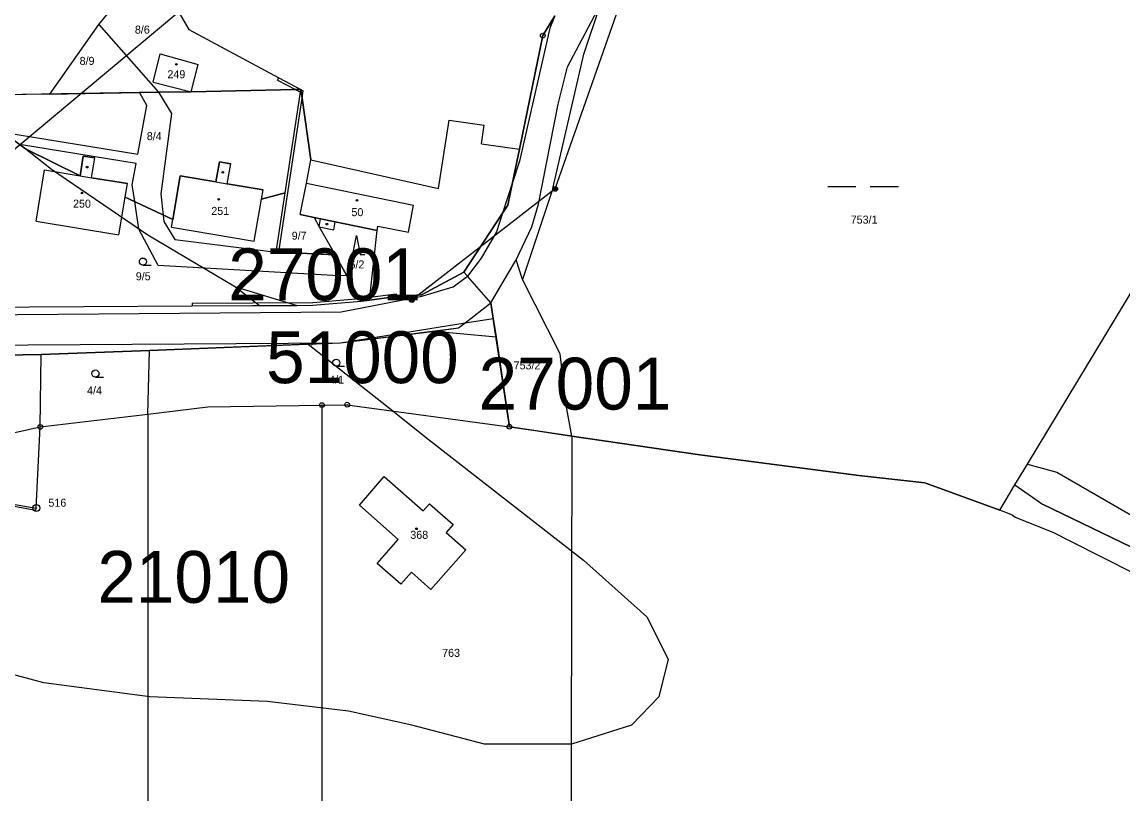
# Model space of a CAD drawing. Extents: x -725765 to -723182, y -1052705 to -1049154.
# Drawn here: x -724492.6 to -724259, y -1051095.6 to -1050931.8 of the extents above; entities that cross this region are included whole.
import ezdxf

# ---------------------------------------------------------------- set-up
doc = ezdxf.new("R2010")
doc.units = 0
for name, color, linetype in [('Vrstva 1', 7, 'Continuous'), ('Vrstva 12', 7, 'Continuous'), ('Vrstva 17', 7, 'Continuous'), ('Vrstva 18', 7, 'Continuous'), ('Vrstva 19', 7, 'Continuous'), ('Vrstva 25', 7, 'Continuous'), ('Vrstva 27', 7, 'Continuous'), ('Vrstva 4', 7, 'Continuous'), ('Vrstva 52', 7, 'Continuous'), ('Vrstva 53', 7, 'Continuous')]:
    doc.layers.add(name, color=color, linetype=linetype)

msp = doc.modelspace()

# ---------------------------------------------------------------- linework, layer by layer
at = {"layer": 'Vrstva 1'}
for points in [[(-724476.27, -1050932.34), (-724466.99, -1050921.02)], [(-724462.55, -1050923.98), (-724457.15, -1050933.43)], [(-724376.7, -1050941.33), (-724369.69, -1050928.08)], [(-724486.65, -1050947.12), (-724476.27, -1050932.34)], [(-724476.27, -1050932.34), (-724463.55, -1050946.69)], [(-724381.97, -1050934.69), (-724379.43, -1050930.49)], [(-724457.15, -1050933.43), (-724438.01, -1050943.64)], [(-724386.92, -1050958.77), (-724381.97, -1050934.69)], [(-724464.71, -1050944.56), (-724463.24, -1050938.58)], [(-724463.24, -1050938.58), (-724455.15, -1050940.8)], [(-724456.63, -1050946.64), (-724455.15, -1050940.8)], [(-724378.71, -1050949.25), (-724376.7, -1050941.33)], [(-724279.02, -1051025.59), (-724228.49, -1050942.01)], [(-724438.01, -1050943.64), (-724433.33, -1050946.13)], [(-724486.65, -1050947.12), (-724467.73, -1050946.77), (-724463.55, -1050946.69)], [(-724464.71, -1050944.56), (-724456.63, -1050946.64)], [(-724463.55, -1050946.69), (-724456.63, -1050946.64)], [(-724456.63, -1050946.64), (-724434.45, -1050946.15)], [(-724436.68, -1050968.08), (-724433.42, -1050946.7)], [(-724434.45, -1050946.15), (-724433.33, -1050946.13)], [(-724433.42, -1050946.7), (-724433.33, -1050946.13)], [(-724433.33, -1050946.13), (-724433.06, -1050947.99)], [(-724486.65, -1050947.12), (-724496.66, -1050947.3)], [(-724433.06, -1050947.99), (-724431.19, -1050961.03)], [(-724382.9, -1050970.46), (-724378.71, -1050949.25)], [(-724498.57, -1050953.71), (-724491.8, -1050958.69)], [(-724404.11, -1050967.13), (-724401.86, -1050952.66)], [(-724401.86, -1050952.66), (-724394.42, -1050953.7)], [(-724394.95, -1050957.67), (-724394.42, -1050953.7)], [(-724394.95, -1050957.67), (-724386.92, -1050958.77)], [(-724491.8, -1050958.69), (-724480.19, -1050964.45)], [(-724480.19, -1050964.45), (-724479.54, -1050960.25)], [(-724479.54, -1050960.25), (-724477.11, -1050960.65)], [(-724477.77, -1050964.85), (-724477.11, -1050960.65)], [(-724388.38, -1050965.85), (-724386.92, -1050958.77)], [(-724451.36, -1050965.74), (-724450.61, -1050961.47)], [(-724450.61, -1050961.47), (-724448.22, -1050961.87)], [(-724448.96, -1050966.14), (-724448.22, -1050961.87)], [(-724432.16, -1050965.97), (-724431.19, -1050961.03)], [(-724431.19, -1050961.03), (-724404.11, -1050967.13)], [(-724489.56, -1050974.07), (-724487.78, -1050963.2)], [(-724487.78, -1050963.2), (-724480.19, -1050964.45)], [(-724477.77, -1050964.85), (-724470.18, -1050966.1)], [(-724460.55, -1050973.74), (-724458.96, -1050964.48)], [(-724458.96, -1050964.48), (-724451.36, -1050965.74)], [(-724470.65, -1050968.96), (-724470.18, -1050966.1)], [(-724448.96, -1050966.14), (-724441.36, -1050967.41)], [(-724441.7, -1050969.38), (-724441.36, -1050967.41)], [(-724433.48, -1050972.68), (-724432.16, -1050965.97)], [(-724389.37, -1050970.69), (-724388.38, -1050965.85)], [(-724471.98, -1050976.99), (-724470.65, -1050968.96)], [(-724470.65, -1050968.96), (-724460.55, -1050973.74)], [(-724443.22, -1050978.31), (-724441.7, -1050969.38)], [(-724441.7, -1050969.38), (-724436.68, -1050968.08)], [(-724438.59, -1050980.62), (-724436.68, -1050968.08)], [(-724398.72, -1050984.87), (-724390.49, -1050972.39)], [(-724390.49, -1050972.39), (-724389.37, -1050970.69)], [(-724384.31, -1050975.24), (-724382.9, -1050970.46)], [(-724489.56, -1050974.07), (-724471.98, -1050976.99)], [(-724460.82, -1050975.33), (-724460.55, -1050973.74)], [(-724433.48, -1050972.68), (-724430.53, -1050973.29)], [(-724430.53, -1050973.29), (-724429.14, -1050973.57)], [(-724430.53, -1050973.29), (-724429.42, -1050975.26)], [(-724429.14, -1050973.57), (-724426.05, -1050974.21)], [(-724426.05, -1050974.21), (-724417.16, -1050976.04)], [(-724460.82, -1050975.33), (-724443.22, -1050978.31)], [(-724429.42, -1050975.26), (-724426.05, -1050981.21)], [(-724418.7, -1050990.2), (-724417.16, -1050976.04)], [(-724387.6, -1050982.26), (-724384.31, -1050975.24)], [(-724438.59, -1050980.62), (-724438.04, -1050980.65)], [(-724438.04, -1050980.65), (-724426.05, -1050981.21)], [(-724426.05, -1050981.21), (-724420.88, -1050990.48)], [(-724392.98, -1050991.37), (-724387.6, -1050982.26)], [(-724386.28, -1050986.41), (-724387.6, -1050982.26)], [(-724407.7, -1050989.71), (-724398.72, -1050984.87)], [(-724397.93, -1050985.76), (-724398.72, -1050984.87)], [(-724392.98, -1050991.37), (-724397.93, -1050985.76)], [(-724375.8, -1051019.67), (-724377.02, -1051013.07), (-724378.31, -1051002.23), (-724386.28, -1050986.41)], [(-724430.78, -1050991.92), (-724420.56, -1050991.06)], [(-724420.88, -1050990.48), (-724420.56, -1050991.06)], [(-724420.56, -1050991.06), (-724418.77, -1050990.82)], [(-724418.77, -1050990.82), (-724413.02, -1050990.06)], [(-724418.77, -1050990.82), (-724418.7, -1050990.2)], [(-724413.02, -1050990.06), (-724407.7, -1050989.71)], [(-724502.49, -1050992.29), (-724456.42, -1050992.05)], [(-724456.42, -1050992.05), (-724430.78, -1050991.92)], [(-724398.47, -1050995.65), (-724392.98, -1050991.37)], [(-724392.48, -1050994.69), (-724392.98, -1050991.37)], [(-724399.85, -1050996.73), (-724398.47, -1050995.65)], [(-724389.04, -1051017.67), (-724392.48, -1050994.69)], [(-724424.9, -1050999.89), (-724399.85, -1050996.73)], [(-724465.46, -1051001.47), (-724424.9, -1050999.89)], [(-724534.5, -1051003.23), (-724488.46, -1051002.37)], [(-724488.68, -1051017.73), (-724488.46, -1051002.37)], [(-724488.46, -1051002.37), (-724465.46, -1051001.47)], [(-724465.84, -1051014.99), (-724465.46, -1051001.47)], [(-724465.84, -1051014.99), (-724453.07, -1051013.46)], [(-724453.07, -1051013.46), (-724428.87, -1051013.08)], [(-724428.87, -1051013.08), (-724423.49, -1051013)], [(-724428.87, -1051013.08), (-724428.86, -1051121.56)], [(-724423.49, -1051013), (-724389.04, -1051017.67)], [(-724488.68, -1051017.73), (-724465.84, -1051014.99)], [(-724465.84, -1051014.99), (-724465.82, -1051346.13)], [(-724516.35, -1051023.82), (-724488.68, -1051017.73)], [(-724489.51, -1051034.92), (-724488.68, -1051017.73)], [(-724375.8, -1051019.67), (-724389.04, -1051017.67)], [(-724375.8, -1051019.67), (-724376.03, -1051121.56)], [(-724348.61, -1051023.67), (-724375.8, -1051019.67)], [(-724314.87, -1051028.04), (-724348.61, -1051023.67)], [(-724281.71, -1051030.03), (-724279.02, -1051025.59)], [(-724279.02, -1051025.59), (-724272.83, -1051027.29)], [(-724420.92, -1051034.33), (-724415.63, -1051028.25)], [(-724415.63, -1051028.25), (-724407.36, -1051035.52)], [(-724300.86, -1051029.58), (-724314.87, -1051028.04)], [(-724272.83, -1051027.29), (-724245.86, -1051042.84)], [(-724284.96, -1051035.41), (-724300.86, -1051029.58)], [(-724284.96, -1051035.41), (-724281.71, -1051030.03)], [(-724281.71, -1051030.03), (-724275.86, -1051034.1)], [(-724513.05, -1051031.07), (-724489.62, -1051035.39)], [(-724489.62, -1051035.39), (-724489.51, -1051034.92)], [(-724412.66, -1051041.58), (-724420.92, -1051034.33)], [(-724407.36, -1051035.52), (-724406.04, -1051034.01)], [(-724406.04, -1051034.01), (-724401.02, -1051038.45)], [(-724282.2, -1051036.42), (-724284.96, -1051035.41)], [(-724248.6, -1051047.26), (-724275.86, -1051034.1)], [(-724282.2, -1051036.42), (-724281.65, -1051036.88)], [(-724281.65, -1051036.88), (-724273.64, -1051040.08)], [(-724401.02, -1051038.45), (-724402.49, -1051040.12)], [(-724402.49, -1051040.12), (-724398.33, -1051043.76)], [(-724273.64, -1051040.08), (-724269.9, -1051041.96)], [(-724417.14, -1051046.7), (-724412.66, -1051041.58)], [(-724269.9, -1051041.96), (-724256.63, -1051048.65)], [(-724398.33, -1051043.76), (-724405.75, -1051052.18)], [(-724412.1, -1051051.09), (-724417.14, -1051046.7)], [(-724409.87, -1051048.55), (-724412.1, -1051051.09)], [(-724405.75, -1051052.18), (-724409.87, -1051048.55)]]:
    msp.add_lwpolyline(points, dxfattribs=at)
at = {"layer": 'Vrstva 12'}
for points in [[(-724379.33, -1050967.22), (-724360.72, -1050914.17)], [(-724501.06, -1050964.51), (-724455.97, -1050926.8)], [(-724379.33, -1050967.22), (-724409.78, -1050990.82)]]:
    msp.add_lwpolyline(points, dxfattribs=at)
at = {"layer": 'Vrstva 25'}
for points in [[(-724321.47, -1050966.69), (-724315.47, -1050966.69)], [(-724312.47, -1050966.69), (-724306.47, -1050966.69)], [(-724422.27, -1050981.12), (-724421.52, -1050977.12), (-724420.77, -1050981.12), (-724419.77, -1050981.12)], [(-724466.88, -1050983.39), (-724465.13, -1050983.39)], [(-724425.83, -1051004.85), (-724424.08, -1051004.85)], [(-724476.96, -1051007.14), (-724475.21, -1051007.14)]]:
    msp.add_lwpolyline(points, dxfattribs=at)
for centre, radius in [((-724381.97, -1050934.69), 0.5), ((-724381.97, -1050934.69), 0.032), ((-724459.79, -1050940.81), 0.175), ((-724478.72, -1050962.6), 0.175), ((-724449.92, -1050963.7), 0.175), ((-724379.33, -1050967.22), 0.5), ((-724379.33, -1050967.22), 0.3), ((-724379.33, -1050967.22), 0.15), ((-724479.82, -1050968.1), 0.175), ((-724450.8, -1050969.42), 0.175), ((-724421.41, -1050969.64), 0.175), ((-724427.81, -1050974.69), 0.175), ((-724466.88, -1050982.64), 0.75), ((-724409.78, -1050990.82), 0.5), ((-724409.78, -1050990.82), 0.3), ((-724409.78, -1050990.82), 0.15), ((-724425.83, -1051004.1), 0.75), ((-724476.96, -1051006.39), 0.75), ((-724428.87, -1051013.08), 0.5), ((-724428.87, -1051013.08), 0.032), ((-724423.49, -1051013), 0.5), ((-724423.49, -1051013), 0.032), ((-724488.68, -1051017.73), 0.5), ((-724488.68, -1051017.73), 0.032), ((-724389.04, -1051017.67), 0.5), ((-724389.04, -1051017.67), 0.032), ((-724489.51, -1051034.92), 0.75), ((-724489.51, -1051034.92), 0.032), ((-724408.8, -1051039.33), 0.175)]:
    msp.add_circle(centre, radius, dxfattribs=at)
at = {"layer": 'Vrstva 27'}
for points in [[(-724467.73, -1050946.77), (-724463.55, -1050946.69)], [(-724463.55, -1050946.69), (-724460.8, -1050951.22)], [(-724467.49, -1050947.01), (-724467.73, -1050946.77)], [(-724466.04, -1050949.53), (-724467.49, -1050947.01)], [(-724467.96, -1050959.88), (-724466.04, -1050949.53)], [(-724460.8, -1050951.22), (-724463.07, -1050968.26)], [(-724496.59, -1050955.16), (-724467.96, -1050959.88)], [(-724468.32, -1050961.84), (-724493.05, -1050957.77)], [(-724469.16, -1050966.35), (-724468.32, -1050961.84)], [(-724468.62, -1050969.92), (-724469.16, -1050966.35)], [(-724467.73, -1050975.77), (-724468.62, -1050969.92)], [(-724463.07, -1050968.26), (-724462.56, -1050972.79)], [(-724462.56, -1050972.79), (-724462.41, -1050974.14)], [(-724462.41, -1050974.14), (-724460.08, -1050977.97)], [(-724463.64, -1050983.46), (-724467.73, -1050975.77)], [(-724460.08, -1050977.97), (-724438.59, -1050980.62)], [(-724438.59, -1050980.62), (-724438.04, -1050980.65)], [(-724438.04, -1050980.65), (-724426.05, -1050981.21)], [(-724426.05, -1050981.21), (-724423.56, -1050985.67)], [(-724426.58, -1050985.61), (-724463.64, -1050983.46)], [(-724423.56, -1050985.67), (-724426.58, -1050985.61)]]:
    msp.add_lwpolyline(points, dxfattribs=at)
at = {"layer": 'Vrstva 4'}
for points in [[(-724373.24, -1050938.62), (-724369.69, -1050928.08)], [(-724379.43, -1050930.49), (-724380.44, -1050933.09)], [(-724380.44, -1050933.09), (-724386.91, -1050961.32)], [(-724379.85, -1050967.15), (-724373.24, -1050938.62)], [(-724438.27, -1050944.13), (-724438.01, -1050943.64)], [(-724438.27, -1050944.13), (-724434.45, -1050946.15)], [(-724434.45, -1050946.15), (-724433.42, -1050946.7)], [(-724433.33, -1050946.13), (-724432.82, -1050946.4)], [(-724433.06, -1050947.99), (-724432.82, -1050946.4)], [(-724438.04, -1050980.65), (-724433.06, -1050947.99)], [(-724386.91, -1050961.32), (-724388.38, -1050965.85)], [(-724480.19, -1050964.45), (-724477.77, -1050964.85)], [(-724451.36, -1050965.74), (-724448.96, -1050966.14)], [(-724432.16, -1050965.97), (-724409.44, -1050970.7)], [(-724388.38, -1050965.85), (-724390.49, -1050972.39)], [(-724379.85, -1050967.15), (-724386.28, -1050986.41)], [(-724410.5, -1050976.41), (-724409.44, -1050970.7)], [(-724390.49, -1050972.39), (-724391.77, -1050976.35)], [(-724429.42, -1050975.26), (-724429.14, -1050973.57)], [(-724426.37, -1050975.87), (-724426.05, -1050974.21)], [(-724429.42, -1050975.26), (-724426.37, -1050975.87)], [(-724417.16, -1050976.04), (-724416.98, -1050975.16)], [(-724416.98, -1050975.16), (-724410.5, -1050976.41)], [(-724391.77, -1050976.35), (-724395.08, -1050981.91)], [(-724395.08, -1050981.91), (-724397.93, -1050985.76)], [(-724401.02, -1050988.01), (-724397.93, -1050985.76)], [(-724407.68, -1050990.01), (-724401.02, -1050988.01)], [(-724430.78, -1050991.32), (-724420.88, -1050990.48)], [(-724424.8, -1050993.31), (-724407.68, -1050990.01)], [(-724420.88, -1050990.48), (-724418.7, -1050990.2)], [(-724418.7, -1050990.2), (-724413.1, -1050989.46)], [(-724413.1, -1050989.46), (-724413.02, -1050990.06)], [(-724502.1, -1050993.92), (-724424.8, -1050993.31)], [(-724456.42, -1050991.45), (-724430.78, -1050991.32)], [(-724456.42, -1050991.45), (-724456.42, -1050992.05)], [(-724424.9, -1050999.89), (-724398.47, -1050995.65)], [(-724398.47, -1050995.65), (-724392.48, -1050994.69)], [(-724502.39, -1051000.4), (-724424.9, -1050999.89)], [(-724517.5, -1051030.06), (-724489.51, -1051034.92)]]:
    msp.add_lwpolyline(points, dxfattribs=at)
at = {"layer": 'Vrstva 52'}
for points in [[(-724379.43, -1050930.49), (-724381.97, -1050934.69), (-724386.92, -1050958.77), (-724388.38, -1050965.85), (-724389.37, -1050970.69), (-724390.49, -1050972.39), (-724398.72, -1050984.87), (-724407.7, -1050989.71), (-724413.02, -1050990.06), (-724418.77, -1050990.82), (-724418.7, -1050990.2), (-724417.16, -1050976.04), (-724426.05, -1050974.21), (-724429.14, -1050973.57), (-724430.53, -1050973.29), (-724433.48, -1050972.68), (-724432.16, -1050965.97), (-724431.19, -1050961.03), (-724433.06, -1050947.99), (-724433.33, -1050946.13), (-724434.45, -1050946.15), (-724456.63, -1050946.64), (-724463.55, -1050946.69), (-724496.66, -1050947.3)], [(-724505.66, -1050947.46), (-724507.01, -1050947.49), (-724498.57, -1050953.71), (-724492.05, -1050958.5)], [(-724492.05, -1050958.5), (-724486.31, -1050963), (-724465.81, -1050977), (-724447.19, -1050988)], [(-724434.15, -1050991.94), (-724430.78, -1050991.92), (-724420.56, -1050991.06), (-724420.88, -1050990.48), (-724426.05, -1050981.21), (-724438.04, -1050980.65), (-724438.59, -1050980.62), (-724436.68, -1050968.08), (-724441.7, -1050969.38), (-724441.36, -1050967.41), (-724448.96, -1050966.14), (-724448.22, -1050961.87), (-724450.61, -1050961.47), (-724451.36, -1050965.74), (-724458.96, -1050964.48), (-724460.55, -1050973.74), (-724470.65, -1050968.96), (-724470.18, -1050966.1), (-724477.77, -1050964.85), (-724477.11, -1050960.65), (-724479.54, -1050960.25), (-724480.19, -1050964.45), (-724491.8, -1050958.69), (-724492.05, -1050958.5)], [(-724447.19, -1050988), (-724434.15, -1050991.94)], [(-724447.19, -1050988), (-724442.15, -1050991.98)], [(-724597.47, -1050993.67), (-724587.33, -1050993.27), (-724576.41, -1050992.85), (-724575.09, -1050992.84), (-724560.62, -1050992.78), (-724536.18, -1050992.47), (-724502.49, -1050992.29), (-724456.42, -1050992.05), (-724442.15, -1050991.98)], [(-724442.15, -1050991.98), (-724434.15, -1050991.94)], [(-724404.9, -1050997.37), (-724399.85, -1050996.73), (-724398.47, -1050995.65), (-724392.98, -1050991.37), (-724392.48, -1050994.69), (-724391.9, -1050998.59)], [(-724431.78, -1051000.16), (-724424.9, -1050999.89), (-724404.9, -1050997.37)], [(-724404.9, -1050997.37), (-724391.9, -1050998.59)], [(-724431.78, -1051000.16), (-724465.46, -1051001.47), (-724488.46, -1051002.37), (-724534.5, -1051003.23), (-724583.61, -1051003.99), (-724583.03, -1051022.13)], [(-724431.78, -1051000.16), (-724413.84, -1051014.31), (-724406.63, -1051020), (-724373.31, -1051046), (-724359.88, -1051058), (-724355.38, -1051067), (-724357.31, -1051075), (-724363.13, -1051081), (-724375.88, -1051085), (-724394.38, -1051085), (-724409.81, -1051081), (-724423.19, -1051078), (-724440.5, -1051076), (-724465.38, -1051075), (-724487.88, -1051072), (-724514.13, -1051065), (-724540.31, -1051055), (-724558.88, -1051045), (-724574.88, -1051033), (-724581.22, -1051024.54), (-724583.03, -1051022.13)], [(-724391.9, -1050998.59), (-724389.04, -1051017.67), (-724383.12, -1051018.56), (-724375.8, -1051019.67), (-724348.61, -1051023.67), (-724314.87, -1051028.04), (-724300.86, -1051029.58), (-724284.96, -1051035.41), (-724281.71, -1051030.03), (-724275.86, -1051034.1), (-724248.6, -1051047.26), (-724233.02, -1051057.13), (-724232.82, -1051057.26), (-724211.08, -1051071.02), (-724195.83, -1051085.51), (-724177.49, -1051101.21), (-724157.41, -1051106.52), (-724150.05, -1051111.15), (-724138.81, -1051113.44), (-724135.56, -1051114.1), (-724121.58, -1051131.09)]]:
    msp.add_lwpolyline(points, dxfattribs=at)

# ---------------------------------------------------------------- texts
at = {"layer": 'Vrstva 17'}
msp.add_text('516 ', height=1.7, dxfattribs=at).set_placement((-724486.94, -1051034.65))
at = {"layer": 'Vrstva 18'}
for s, p in [('8/6', (-724468.58, -1050934.28)), ('8/9', (-724480.32, -1050940.91)), ('8/4', (-724466.05, -1050956.88)), ('753/1', (-724316.59, -1050974.59)), ('9/7', (-724435.28, -1050978)), ('6/2', (-724423.02, -1050984.1)), ('9/5', (-724468.39, -1050986.61)), ('753/2', (-724388.17, -1051005.51)), ('4/1', (-724427.32, -1051008.52)), ('4/4', (-724478.73, -1051010.81)), ('763', (-724403.34, -1051066.5))]:
    msp.add_text(s, height=1.7, dxfattribs=at).set_placement(p)
at = {"layer": 'Vrstva 19'}
for s, p in [('249', (-724461.67, -1050943.75)), ('250', (-724481.71, -1050971.2)), ('251', (-724452.36, -1050972.74)), ('50', (-724422.6, -1050973)), ('368', (-724410.1, -1051041.46))]:
    msp.add_text(s, height=1.7, dxfattribs=at).set_placement(p)
at = {"layer": 'Vrstva 53'}
for s, p in [('27001', (-724448.75, -1050990.85)), ('51000', (-724440.72, -1051008.43)), ('27001', (-724395.59, -1051014.03)), ('21010', (-724476.55, -1051055.03))]:
    msp.add_text(s, height=11, dxfattribs=at).set_placement(p)

doc.saveas('drawing.dxf')
